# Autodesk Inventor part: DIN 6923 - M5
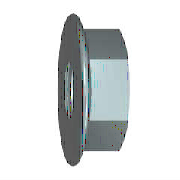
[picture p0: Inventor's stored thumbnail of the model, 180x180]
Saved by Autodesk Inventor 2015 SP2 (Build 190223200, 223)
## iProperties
IsCustomPart: 0
Created: 2012-02
Part Number: DIN 6923 - M5
Material: Stahl, weich
Description: Sechskantmutter
Document SubType Name: Modeling
Standard: DIN 6923
Designer: Dan
Standards Organization: DIN
Language: de-DE
Size Designation: M5
Categories: <MemberInstance><Categories><Category DisplayName="Verbindungselemente" InternalName="e4da775c-781d-43d5-af7c-5136215cf5a6" Mnemonic="FSTN"><Category DisplayNam
Density: 7.85 g/cm^3
Appearance: Halbpoliert
Author: Dan
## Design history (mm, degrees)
sketch "Skizze1"
  geometry: L1 (-1.204, 0)-(6.034, 0) reference; L2 (2.523, 4)-(1.906, 5.323); L3 (2.523, 4)-(5, 4); L4 (5, 4)-(5, 0); L5 (2.523, 4)-(2.523, 0); L6 (0, -1.218)-(0, 7.305) reference; A1 r 1 centre (1, 4.9) between (1.906, 5.323) and (0, 4.9); 1 further point
  constraints: 8 end point, 3 point on line, 2 perpendicular, 2 point on circle, 2 tangent, 1 centre point, 1 parallel
  dimensions: "d2" = 8 diameter of L3 L1 (= SW); "d4" = 11.8 dimension on A1 L1 (= LADI); "d5" = 1 radius of A1 (= PHH); "d15" = 5 distance between parallel lines of L4 L6 (= KOH); "d16" = 25 deg angle of L6 L2 (= KEWI)
revolve "Ring" sketch "Skizze1" stored, may be unused: angle "d8" = 90 deg
sketch "Skizze2"
  geometry: L1 (-4, -2.309)-(-4, 2.309); L2 (-4, 2.309)-(0, 4.619); L3 (0, 4.619)-(4, 2.309); L4 (4, 2.309)-(4, -2.309); L5 (4, -2.309)-(0, -4.619); L6 (0, -4.619)-(-4, -2.309); C1 r 4.9 at (0, 0); C2 r 4.9 at (0, 0) reference; 1 further point
  constraints: 12 end point, 1 centre point, 1 coincident, 1 vertical, 11 other
  dimensions: "d6" = 9.2376 distance of L5.end L2.end (= 1.1547 x SW)
extrude "Körper" join sketch "Skizze2" distance "d7" = 5 (= KOH); taper "d9" = 0 deg
sketch "Skizze3"
  geometry: L1 (2.235, 4.619)-(5, 4.619) reference; L2 (5, 2.309)-(5, 4.619) reference; L3 (0, -4.9)-(0, 4.9) reference; L4 (-1, 0)-(6, 0) reference; L5 (4.834, 4.619)-(5, 4)
  constraints: 2 end point, 2 point on line
  dimensions: "d10" = 15 deg angle of L2 L5 (= ANG1); "d11" = 8 diameter of L5.end L4 (= SW0)
revolve "Fase1" sketch "Skizze3" stored, may be unused: angle "d24" = 90 deg
sketch "Skizze4"
  geometry: C1 r 4.9 at (0, 0) reference; 1 further point
  constraints: 1 coincident
hole "Gewinde" sketch "Skizze4" at (0, 0) diameter "d25" = 4.134; stored, may be unused: countersink angle "d29" = 82 deg, drill point angle "d31" = 118 deg; dims "d26" = 6, "d27" = 4, "d28" = 2, "d30" = 8
workaxis "Work Axis1"
workplane "Work Plane1"
body "Solid1"
chamfer "Fase2" distance "d12" = 0.43301 (= -0.5 x GD1 + 0.5 x NND); stored, may be unused: angle "d13" = 30 deg, second distance "d46" = 0.43301 (= -0.5 x GD1 + 0.5 x NND)
chamfer "Fase3" distance "d51" = 0.43301 (= -0.5 x GD1 + 0.5 x NND); stored, may be unused: second distance "d52" = 2, angle "d53" = 45 deg
other parameters: "ANG1" = 15 deg [user parameter; used in 1 equation term], "KEWI" = 25 deg [user parameter; used in 1 equation term], "NND" = 5 [user parameter; used in 4 equation terms], "LADI" = 11.8 [user parameter; used in 2 equation terms], "SW" = 8 [user parameter; used in 4 equation terms], "PHH" = 1 (= RR) [user parameter; used in 2 equation terms], "KOH" = 5 (= NND) [user parameter; used in 2 equation terms], "SW0" = 8 (= SW) [user parameter; used in 1 equation term], "GD1" = 4.13397 (computed from THREADDIA, PTC, TOA) [user parameter; used in 3 equation terms], "d1" = 11.8 (= LADI), "d3" = 1 (= PHH), "d45" = 0, "d47" = 0, "d49" = 0, "d54" = 0, "GUL" = 0.43301 (= 0.541266 x PTC) [user parameter], "TPU" = 12.5 (computed from PTC) [user parameter], "RR" = 1 [user parameter; used in 1 equation term], "THREADDIA" = 5 [user parameter; used in 1 equation term], "TOA" = 30 deg [user parameter; used in 1 equation term], "PTC" = 0.8 [user parameter; used in 4 equation terms], "GAL" = 0.43301 (= 0.541266 x PTC) [user parameter], "E0" = 9.24 (= 1.155 x SW) [user parameter]
